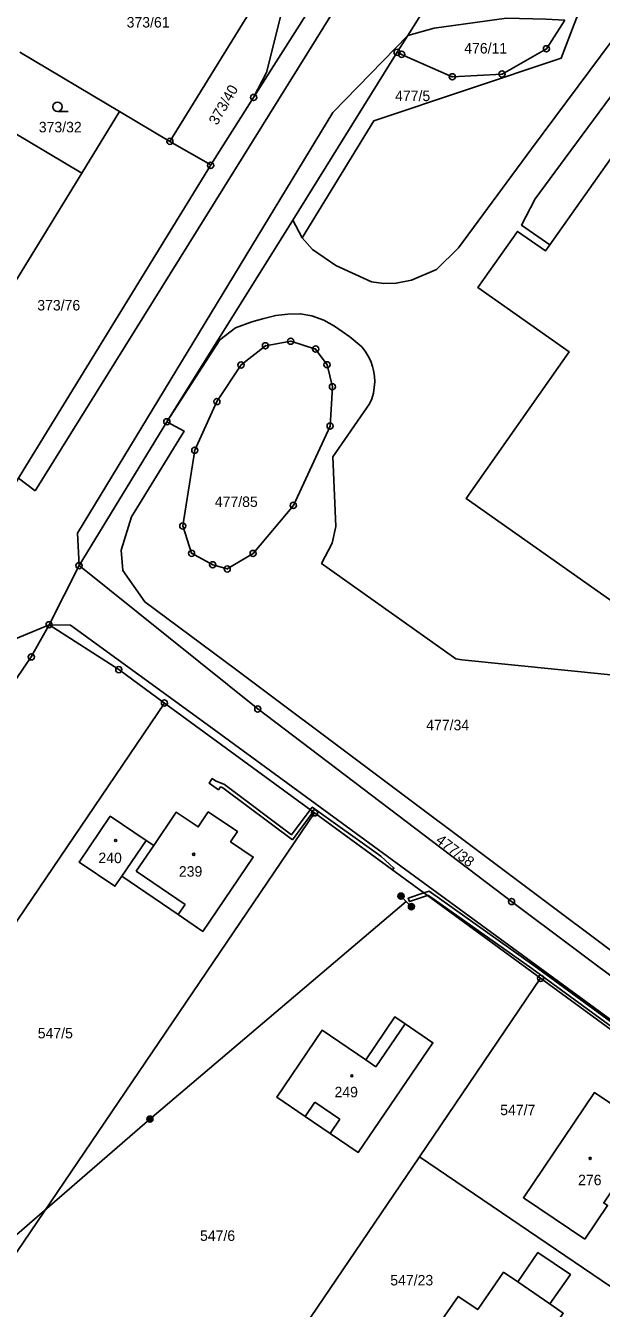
# Model space of a CAD drawing. Extents: x -758582 to -751794, y -998770 to -994350.
# Drawn here: x -754248.1 to -754154.9, y -997140.7 to -996932.8 of the extents above; entities that cross this region are included whole.
import ezdxf

# ---------------------------------------------------------------- set-up
doc = ezdxf.new("R2010")
doc.units = 0
for name, color, linetype in [('Hranice parcel', 7, 'Continuous'), ('Parcelní čísla', 7, 'Continuous'), ('Poz předměty', 7, 'Continuous'), ('Vnitřní kresba', 7, 'Continuous'), ('Věcná břemena k části', 7, 'Continuous'), ('Značky bodu BP', 7, 'Continuous'), ('Značky budov', 7, 'Continuous'), ('Značky kultur', 7, 'Continuous')]:
    doc.layers.add(name, color=color, linetype=linetype)

msp = doc.modelspace()

# ---------------------------------------------------------------- linework, layer by layer
at = {"layer": 'Hranice parcel'}
for p, q in [((-754211.2, -996944.43), (-754193.13, -996915.94)), ((-754186.22, -996934.38), (-754178.17, -996921.51)), ((-754210.71, -996928.81), (-754224.77, -996951.55)), ((-754187.94, -996937.12), (-754186.22, -996934.38)), ((-754232.94, -996946.73), (-754249.07, -996937.1)), ((-754187.94, -996937.12), (-754204.83, -996964.32)), ((-754218.11, -996955.35), (-754211.2, -996944.43)), ((-754239.04, -996956.72), (-754254.94, -996947.27)), ((-754239.04, -996956.72), (-754232.94, -996946.73)), ((-754232.94, -996946.73), (-754224.77, -996951.55)), ((-754224.77, -996951.55), (-754218.11, -996955.35)), ((-754253.88, -996980.88), (-754239.04, -996956.72)), ((-754204.83, -996964.32), (-754225.26, -996997.02)), ((-754204.83, -996964.32), (-754203.34, -996967.22)), ((-754225.26, -996997.02), (-754239.48, -997020.33)), ((-754244.34, -997029.93), (-754239.48, -997020.33)), ((-754280.16, -997123), (-754225.65, -997042.61)), ((-754225.65, -997042.61), (-754201.32, -997060.42)), ((-754255.21, -997139.91), (-754201.32, -997060.42)), ((-754201.32, -997060.42), (-754164.7, -997087.23)), ((-754228.63, -997064.88), (-754232.56, -997070.67)), ((-754184.34, -997116.2), (-754164.7, -997087.23)), ((-754201.98, -997142.22), (-754184.34, -997116.2))]:
    msp.add_line(p, q, dxfattribs=at)
for points in [[(-754195.49, -996906.63), (-754205.49, -996925.91), (-754209.12, -996940.39), (-754211.2, -996944.43)], [(-754203.34, -996967.22), (-754191.72, -996948.22), (-754161.36, -996938.09), (-754159.26, -996932.55), (-754157.69, -996928.51), (-754157.17, -996926.8), (-754154.96, -996920.37)], [(-754105.46, -996939.21), (-754121.86, -996927.74), (-754127.57, -996923.78), (-754145.56, -996924.99), (-754166.15, -996952.75), (-754178.02, -996968.84), (-754181.56, -996972.31), (-754185.62, -996974.05), (-754188.1, -996974.56), (-754190.09, -996974.57), (-754192.07, -996974.3), (-754197.88, -996971.69), (-754201.66, -996969.1), (-754203.34, -996967.22)], [(-754160.79, -996931.92), (-754163.75, -996936.54), (-754170.94, -996940.64), (-754179, -996941.08), (-754187.22, -996937.45), (-754187.94, -996937.12)], [(-754186.22, -996934.38), (-754181.92, -996933.2), (-754170.21, -996931.59), (-754163.83, -996931.75), (-754160.79, -996931.92)], [(-754163.22, -996968.34), (-754167.78, -996965.13), (-754165.6, -996960.89), (-754160.73, -996954.3), (-754150.63, -996940.6)], [(-754142.47, -996945.71), (-754145.67, -996943.45), (-754163.22, -996968.34)], [(-754218.11, -996955.35), (-754218.17, -996955.44), (-754248.54, -997004.94), (-754249.29, -997006.16), (-754252.12, -997011.03)], [(-754163.22, -996968.34), (-754163.91, -996969.32), (-754168.44, -996966.15), (-754174.84, -996975.25), (-754160.04, -996985.68), (-754176.78, -997009.44), (-754112.9, -997054.45), (-754102.9, -997040.42), (-754083.31, -997054.17)], [(-754225.26, -996997.02), (-754216.68, -996983.71), (-754214.12, -996981.81), (-754211.46, -996980.82), (-754209.55, -996980.26), (-754207.61, -996979.8), (-754205.64, -996979.55), (-754203.63, -996979.49), (-754201.74, -996979.84), (-754199.83, -996980.56), (-754198.07, -996981.54), (-754195.62, -996983.22), (-754193.68, -996984.85)], [(-754213.24, -996987.8), (-754209.28, -996984.69), (-754205.19, -996983.95), (-754201.15, -996985.22), (-754199.3, -996987.77), (-754198.42, -996991.34), (-754198.8, -996997.72), (-754204.75, -997010.57), (-754211.28, -997018.36), (-754215.48, -997020.88), (-754217.83, -997020.2), (-754221.26, -997018.34), (-754222.67, -997013.91), (-754220.73, -997001.63), (-754217.15, -996993.73), (-754213.24, -996987.8)], [(-754193.68, -996984.85), (-754193.11, -996985.58), (-754192.62, -996986.36), (-754192.22, -996987.2), (-754191.92, -996988.07), (-754191.76, -996988.71), (-754191.62, -996989.63), (-754191.58, -996990.55), (-754191.64, -996991.47), (-754191.79, -996992.39), (-754192.05, -996993.27), (-754192.4, -996994.13)], [(-754192.4, -996994.13), (-754198.35, -997002.7), (-754197.86, -997014.01), (-754198.49, -997016.69), (-754200.19, -997019.97), (-754178.43, -997035.46), (-754177.44, -997035.63), (-754153.32, -997038.06), (-754146, -997041.17), (-754136.25, -997046.36), (-754120.79, -997057.26)], [(-754225.26, -996997.02), (-754222.47, -996998.51), (-754230.99, -997012.45), (-754232.65, -997017.82), (-754232.38, -997021.15), (-754228.83, -997026.23), (-754214.12, -997037.13), (-754125.75, -997103.38), (-754123.21, -997098.99), (-754112.91, -997106.08), (-754108.02, -997098.69)], [(-754239.48, -997020.33), (-754210.52, -997043.57), (-754169.4, -997074.8), (-754120.65, -997111.31), (-754119.64, -997110)], [(-754298.61, -997110.48), (-754287.65, -997094.76), (-754247.23, -997035.13), (-754244.34, -997029.93)], [(-754244.34, -997029.93), (-754233.04, -997037.19), (-754225.65, -997042.61)], [(-754232.56, -997070.67), (-754233.66, -997072.32), (-754239.48, -997068.41), (-754234.42, -997060.97), (-754228.63, -997064.88)], [(-754228.63, -997064.88), (-754227.38, -997065.7), (-754223.73, -997060.33), (-754220.17, -997062.7), (-754218.54, -997060.27), (-754213.81, -997063.46), (-754214.93, -997065.09), (-754211.25, -997067.58), (-754219.44, -997079.64), (-754223.41, -997076.9), (-754232.56, -997070.67)], [(-754164.7, -997087.23), (-754151.28, -997097.05), (-754137.91, -997106.85)], [(-754186.65, -997094.6), (-754182.14, -997097.69), (-754194.23, -997115.47), (-754198.79, -997112.38), (-754202.83, -997109.64), (-754207.46, -997106.5), (-754200.1, -997095.65), (-754193.04, -997100.44), (-754188.33, -997093.49), (-754186.65, -997094.6)], [(-754157.54, -997129.54), (-754167.48, -997122.81), (-754155.97, -997105.77), (-754146.02, -997112.46), (-754149.33, -997117.34), (-754149.94, -997116.93), (-754154.45, -997123.65), (-754153.84, -997124.06), (-754157.54, -997129.54)], [(-754184.34, -997116.2), (-754151.83, -997138.22), (-754151.48, -997138.46)], [(-754178.7, -997146.53), (-754181.86, -997144.36), (-754178.03, -997138.8), (-754174.88, -997140.95), (-754170.7, -997134.88), (-754168.4, -997136.45), (-754165.12, -997131.69), (-754159.87, -997135.28), (-754163.18, -997140.04), (-754161.02, -997141.54), (-754169.03, -997153.18), (-754178.7, -997146.53)]]:
    msp.add_lwpolyline(points, dxfattribs=at)
at = {"layer": 'Poz předměty'}
for p, q in [((-754187.32, -997073.91), (-754186.47, -997074.76)), ((-754228.01, -997110.07), (-754186.47, -997074.76)), ((-754185.62, -997075.62), (-754186.47, -997074.76)), ((-754266.75, -997143.66), (-754228.01, -997110.07))]:
    msp.add_line(p, q, dxfattribs=at)
for centre, radius in [((-754187.32, -997073.91), 0.5), ((-754187.32, -997073.91), 0.4), ((-754187.32, -997073.91), 0.3), ((-754187.32, -997073.91), 0.2), ((-754187.32, -997073.91), 0.1), ((-754185.62, -997075.62), 0.5), ((-754185.62, -997075.62), 0.4), ((-754185.62, -997075.62), 0.3), ((-754185.62, -997075.62), 0.2), ((-754185.62, -997075.62), 0.1), ((-754228.01, -997110.07), 0.5), ((-754228.01, -997110.07), 0.4), ((-754228.01, -997110.07), 0.3), ((-754228.01, -997110.07), 0.2), ((-754228.01, -997110.07), 0.1)]:
    msp.add_circle(centre, radius, dxfattribs=at)
at = {"layer": 'Vnitřní kresba'}
for p, q in [((-754179.03, -996899.53), (-754246.61, -997008.22)), ((-754198.38, -996946.89), (-754186.22, -996934.38)), ((-754239.74, -997015.08), (-754198.38, -996946.89)), ((-754249.29, -997006.16), (-754246.61, -997008.22)), ((-754239.74, -997015.08), (-754239.48, -997020.33)), ((-754250.41, -997032.48), (-754244.34, -997029.93)), ((-754240.85, -997030), (-754244.34, -997029.93)), ((-754218.7, -997046.08), (-754240.85, -997030)), ((-754218.7, -997046.08), (-754077.49, -997149.58)), ((-754227.38, -997065.7), (-754230.21, -997069.86)), ((-754230.21, -997069.86), (-754222.28, -997075.26)), ((-754222.28, -997075.26), (-754223.41, -997076.9)), ((-754191.38, -997101.57), (-754186.65, -997094.6)), ((-754193.04, -997100.44), (-754191.38, -997101.57)), ((-754201.26, -997107.32), (-754202.83, -997109.64)), ((-754197.22, -997110.07), (-754201.26, -997107.32)), ((-754198.79, -997112.38), (-754197.22, -997110.07)), ((-754168.4, -997136.45), (-754163.18, -997140.04))]:
    msp.add_line(p, q, dxfattribs=at)
at = {"layer": 'Věcná břemena k části'}
for points in [[(-754204.92, -997064.81), (-754201.53, -997060.27), (-754202.01, -997059.92), (-754205.04, -997063.97), (-754215.94, -997055.81), (-754217.4, -997055.22), (-754217.89, -997054.86), (-754218.42, -997055.58), (-754216.9, -997056.67), (-754216.56, -997056.21), (-754216.2, -997056.35)], [(-754188.71, -997069.65), (-754188.45, -997069.37), (-754190.61, -997067.45), (-754201.7, -997059.51), (-754202.01, -997059.92), (-754201.32, -997060.42)], [(-754183.59, -997073.4), (-754186.14, -997074.24), (-754185.96, -997074.81), (-754183, -997073.83)], [(-754183.59, -997073.4), (-754183, -997073.83), (-754182.87, -997073.79), (-754166.13, -997085.67), (-754137.29, -997106.72), (-754092.06, -997139.37), (-754089.28, -997133.79), (-754087.85, -997132.03), (-754088.35, -997131.69), (-754089.79, -997133.46), (-754092.33, -997138.58), (-754108.37, -997126.95), (-754136.94, -997106.23), (-754165.78, -997085.18), (-754182.77, -997073.13)]]:
    msp.add_lwpolyline(points, close=True, dxfattribs=at)
at = {"layer": 'Značky bodu BP'}
for centre, radius in [((-754187.94, -996937.12), 0.5), ((-754187.94, -996937.12), 0.0303), ((-754187.22, -996937.45), 0.5), ((-754163.75, -996936.54), 0.5), ((-754163.75, -996936.54), 0.0303), ((-754187.22, -996937.45), 0.0303), ((-754179, -996941.08), 0.5), ((-754179, -996941.08), 0.0303), ((-754170.94, -996940.64), 0.5), ((-754170.94, -996940.64), 0.0303), ((-754211.2, -996944.43), 0.5), ((-754211.2, -996944.43), 0.0303), ((-754224.77, -996951.55), 0.5), ((-754224.77, -996951.55), 0.0303), ((-754218.17, -996955.44), 0.5), ((-754218.17, -996955.44), 0.0303), ((-754209.28, -996984.69), 0.5), ((-754209.28, -996984.69), 0.0303), ((-754205.19, -996983.95), 0.5), ((-754205.19, -996983.95), 0.0303), ((-754201.15, -996985.22), 0.5), ((-754201.15, -996985.22), 0.0303), ((-754213.24, -996987.8), 0.5), ((-754213.24, -996987.8), 0.0303), ((-754199.3, -996987.77), 0.5), ((-754199.3, -996987.77), 0.0303), ((-754198.42, -996991.34), 0.5), ((-754217.15, -996993.73), 0.5), ((-754198.42, -996991.34), 0.0303), ((-754217.15, -996993.73), 0.0303), ((-754225.26, -996997.02), 0.5), ((-754225.26, -996997.02), 0.0303), ((-754198.8, -996997.72), 0.5), ((-754198.8, -996997.72), 0.0303), ((-754220.73, -997001.63), 0.5), ((-754220.73, -997001.63), 0.0303), ((-754204.75, -997010.57), 0.5), ((-754204.75, -997010.57), 0.0303), ((-754222.67, -997013.91), 0.5), ((-754222.67, -997013.91), 0.0303), ((-754221.26, -997018.34), 0.5), ((-754211.28, -997018.36), 0.5), ((-754239.48, -997020.33), 0.5), ((-754239.48, -997020.33), 0.0303), ((-754221.26, -997018.34), 0.0303), ((-754217.83, -997020.2), 0.5), ((-754217.83, -997020.2), 0.0303), ((-754211.28, -997018.36), 0.0303), ((-754215.48, -997020.88), 0.5), ((-754215.48, -997020.88), 0.0303), ((-754244.34, -997029.93), 0.5), ((-754244.34, -997029.93), 0.0303), ((-754247.23, -997035.13), 0.5), ((-754247.23, -997035.13), 0.0303), ((-754233.04, -997037.19), 0.5), ((-754233.04, -997037.19), 0.0303), ((-754225.65, -997042.61), 0.5), ((-754225.65, -997042.61), 0.0303), ((-754210.52, -997043.57), 0.5), ((-754210.52, -997043.57), 0.0303), ((-754201.32, -997060.42), 0.5), ((-754201.32, -997060.42), 0.0303), ((-754169.4, -997074.8), 0.5), ((-754169.4, -997074.8), 0.0303), ((-754164.7, -997087.23), 0.5), ((-754164.7, -997087.23), 0.0303)]:
    msp.add_circle(centre, radius, dxfattribs=at)
at = {"layer": 'Značky budov'}
for centre in [(-754233.55, -997064.9), (-754220.9, -997067.14), (-754195.29, -997103.04), (-754156.67, -997116.44)]:
    msp.add_circle(centre, 0.175, dxfattribs=at)
at = {"layer": 'Značky kultur'}
msp.add_line((-754242.98, -996946.7), (-754241.23, -996946.7), dxfattribs=at)
msp.add_circle((-754242.98, -996945.95), 0.75, dxfattribs=at)

# ---------------------------------------------------------------- texts
at = {"layer": 'Parcelní čísla'}
for s, p in [('373/61', (-754231.77, -996933.1)), ('476/11', (-754177.07, -996937.31)), ('477/5', (-754188.27, -996945.03)), ('373/32', (-754246.01, -996950.09)), ('373/76', (-754246.25, -996978.97)), ('477/85', (-754217.48, -997010.83)), ('477/34', (-754183.23, -997047.03)), ('240', (-754236.35, -997068.57)), ('239', (-754223.31, -997070.76)), ('547/5', (-754246.17, -997096.98)), ('249', (-754198.09, -997106.53)), ('547/7', (-754171.24, -997109.43)), ('276', (-754158.62, -997120.78)), ('547/6', (-754219.88, -997129.81)), ('547/23', (-754189.05, -997137.03))]:
    msp.add_text(s, height=1.7, dxfattribs=at).set_placement(p)
for s, rotation, p in [('373/40', 60, (-754217.11, -996949.05)), ('477/38', 323, (-754181.81, -997065.13))]:
    msp.add_text(s, height=1.7, rotation=rotation, dxfattribs=at).set_placement(p)

doc.saveas('drawing.dxf')
